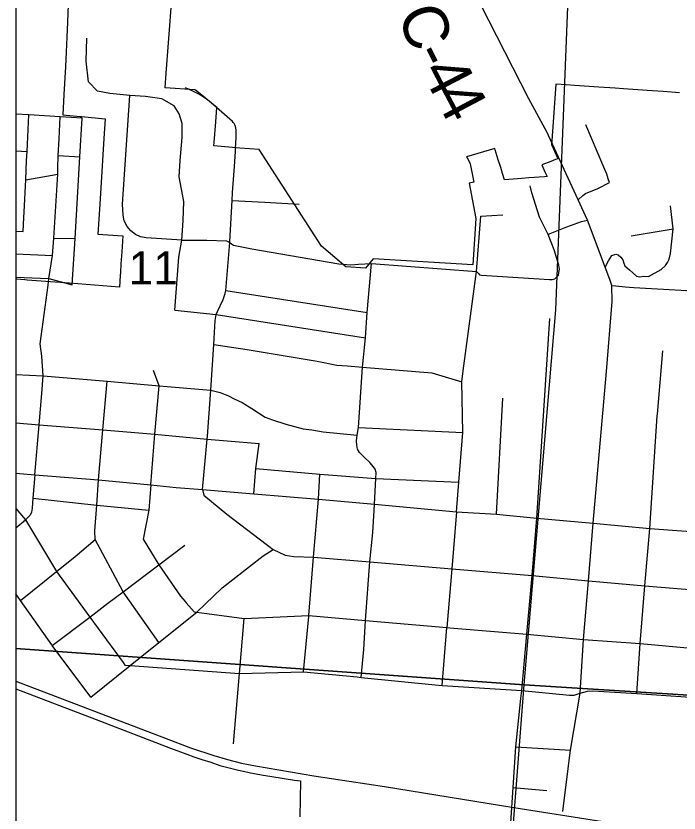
# Model space of a CAD drawing. Extents: x 39.8 to 73.8, y 13 to 35.
# Drawn here: x 41.863 to 42.701, y 32.071 to 33.079 of the extents above; entities that cross this region are included whole.
import ezdxf

# ---------------------------------------------------------------- set-up
doc = ezdxf.new("R2010")
doc.units = 0
for name, color, linetype in [('GM_X_City_Street', 7, 'Continuous'), ('GM_X_Corporation', 7, 'Continuous'), ('GM_X_County_Road', 7, 'Continuous'), ('GM_X_County_Road_Text', 7, 'Continuous'), ('GM_X_Rail_Line', 7, 'Continuous'), ('GM_X_Section_Text', 7, 'Continuous'), ('GM_X_State_Route', 7, 'Continuous'), ('GM_X_Township_Road', 7, 'Continuous')]:
    doc.layers.add(name, color=color, linetype=linetype)

msp = doc.modelspace()

# ---------------------------------------------------------------- linework, layer by layer
at = {"layer": 'GM_X_City_Street'}
for p, q in [((42.445, 32.756), (42.4502, 32.8257)), ((42.4502, 32.8257), (42.4779, 32.8274)), ((42.6401, 32.8009), (42.6933, 32.8099)), ((42.1281, 32.7318), (42.3066, 32.7041)), ((42.5212, 32.444), (42.5375, 32.6967)), ((42.6733, 32.5756), (42.6804, 32.6557)), ((42.4702, 32.4494), (42.4783, 32.5959)), ((42.2958, 32.5589), (42.4276, 32.5524)), ((41.863, 32.4566), (41.8751, 32.4421)), ((41.863, 32.4319), (41.8751, 32.4421)), ((42.2262, 32.2501), (42.2328, 32.32)), ((42.4014, 32.2327), (42.4072, 32.3062)), ((42.4945, 32.1553), (42.5635, 32.1509)), ((42.5539, 32.0735), (42.5623, 32.1412)), ((42.4911, 32.1038), (42.5336, 32.1001))]:
    msp.add_line(p, q, dxfattribs=at)
for points in [[(42.0636, 32.7071), (42.0687, 32.774), (42.0727, 32.7954), (42.0743, 32.8202), (42.0751, 32.8445), (42.0693, 32.8754), (42.0706, 32.8963), (42.0731, 32.9253), (42.0731, 32.9428), (42.0693, 32.9551), (42.0629, 32.9654), (42.0471, 32.9743), (42.0267, 32.9773), (42.007, 32.9782), (41.9815, 32.9807), (41.9662, 32.9837), (41.9545, 32.9955), (41.9516, 33.0217), (41.9524, 33.0509)], [(42.0727, 32.7954), (42.0274, 32.7984), (42.0204, 32.7999), (42.0142, 32.8027), (42.0083, 32.8072), (42.0037, 32.8129), (41.9999, 32.82), (41.9985, 32.8273), (41.9978, 32.8411), (42.007, 32.9782)], [(42.5734, 32.8466), (42.579, 32.8518), (42.5825, 32.8546), (42.598, 32.861), (42.6129, 32.8684), (42.6111, 32.8729), (42.6096, 32.879), (42.6043, 32.8906), (42.5828, 32.9414)], [(42.5353, 32.8027), (42.5243, 32.8248), (42.5147, 32.8555), (42.5125, 32.8643)], [(42.136, 32.8456), (42.1774, 32.8434), (42.221, 32.8409)], [(42.6073, 32.7616), (42.6114, 32.7693), (42.6159, 32.776), (42.6209, 32.7778), (42.6239, 32.7771), (42.6273, 32.7741), (42.6297, 32.7707), (42.6308, 32.7665), (42.6323, 32.7631), (42.6381, 32.7581), (42.6429, 32.754), (42.6468, 32.7499), (42.6511, 32.7491), (42.6558, 32.7499), (42.6623, 32.7497), (42.6782, 32.7583), (42.6837, 32.7635), (42.6862, 32.7674), (42.6882, 32.7717), (42.6899, 32.7786), (42.6933, 32.8099), (42.6898, 32.839)], [(42.0727, 32.7954), (42.1043, 32.7957), (42.1291, 32.7946), (42.1313, 32.7938), (42.1334, 32.7928), (42.1355, 32.7908), (42.1378, 32.7891), (42.1612, 32.7847), (42.2707, 32.7657), (42.286, 32.7644), (42.2957, 32.7654), (42.3122, 32.7662), (42.445, 32.756)], [(42.3154, 32.4537), (42.3158, 32.4617), (42.3178, 32.4944), (42.318, 32.5018), (42.3169, 32.5061), (42.3149, 32.5089), (42.3099, 32.5146), (42.3032, 32.5208), (42.297, 32.5271), (42.2943, 32.5313), (42.2936, 32.5363), (42.2934, 32.5418), (42.2941, 32.5492), (42.2958, 32.5589), (42.301, 32.6351), (42.3048, 32.6723), (42.3066, 32.7041), (42.3122, 32.7662)], [(42.616, 32.7381), (42.6207, 32.7378), (42.6326, 32.7364), (42.6437, 32.7356), (42.7479, 32.7297), (42.7652, 32.7282), (42.7801, 32.7247), (42.9726, 32.7075), (43.0218, 32.7079)], [(42.0636, 32.7071), (42.116, 32.7018), (42.3048, 32.6723)], [(42.0334, 32.4865), (42.0383, 32.5502), (42.0438, 32.6114), (42.0366, 32.6308)], [(41.9632, 32.4173), (41.9627, 32.4282), (41.9653, 32.4608), (41.9674, 32.4925), (41.9728, 32.5557), (41.9782, 32.6173)], [(42.4196, 32.4523), (42.4227, 32.4897), (42.4276, 32.5524), (42.4261, 32.6166)], [(42.109, 32.6059), (42.1208, 32.6031), (42.1315, 32.5988), (42.1386, 32.5951), (42.1487, 32.5902), (42.1609, 32.5826), (42.1779, 32.5718), (42.1869, 32.5683), (42.2041, 32.5631), (42.2258, 32.5573), (42.2366, 32.5557), (42.2511, 32.5535), (42.2941, 32.5492)], [(42.6473, 32.2227), (42.6514, 32.2858), (42.6575, 32.3586), (42.664, 32.4313), (42.6731, 32.5736), (42.6733, 32.5756)], [(41.863, 32.5647), (41.8923, 32.5621), (41.9728, 32.5557), (42.0383, 32.5502), (42.1047, 32.5442), (42.1702, 32.5387)], [(42.1634, 32.4749), (42.1661, 32.507), (42.1702, 32.5387)], [(42.1661, 32.507), (42.2468, 32.5), (42.3178, 32.4944), (42.4227, 32.4897)], [(42.2328, 32.32), (42.2328, 32.321), (42.2388, 32.3948), (42.2453, 32.4684), (42.2468, 32.5)], [(42.0334, 32.4865), (42.0307, 32.4541), (42.0237, 32.4175), (42.0434, 32.3852), (42.0709, 32.3457), (42.0769, 32.3388)], [(41.8843, 32.4696), (41.9653, 32.4608), (42.0307, 32.4541)], [(42.299, 32.243), (42.3023, 32.2783), (42.3045, 32.315), (42.3102, 32.389), (42.3139, 32.4259), (42.3154, 32.4537)], [(41.8688, 32.3402), (41.9141, 32.3767), (41.9376, 32.3956), (41.9632, 32.4173)], [(41.9089, 32.2833), (41.9562, 32.3192), (41.9792, 32.3366), (41.9983, 32.351), (42.0434, 32.3852), (42.0765, 32.4102)], [(42.0436, 32.2871), (41.9983, 32.351), (41.9632, 32.4173)], [(41.9576, 32.2181), (42.0074, 32.258), (42.0436, 32.2871), (42.0914, 32.3255), (42.1234, 32.356), (42.1753, 32.3967), (42.188, 32.4046)], [(41.9576, 32.2181), (41.9089, 32.2833), (41.9085, 32.2839), (41.8688, 32.3402), (41.863, 32.3485)], [(42.0769, 32.3388), (42.0782, 32.3373), (42.0882, 32.3259), (42.0914, 32.3255), (42.1514, 32.3174), (42.2328, 32.321), (42.3045, 32.315), (42.4072, 32.3062)], [(42.1379, 32.1588), (42.1453, 32.2479), (42.1514, 32.3174)], [(42.5801, 32.291), (42.6514, 32.2858), (42.7207, 32.2794), (42.8082, 32.2626), (42.9031, 32.2555), (42.909, 32.255)], [(42.5623, 32.1412), (42.5635, 32.1509), (42.5756, 32.2229)]]:
    msp.add_lwpolyline(points, dxfattribs=at)
at = {"layer": 'GM_X_Corporation'}
for points in [[(43.3481, 29.9766), (43.3525, 30.036), (43.3561, 30.0855), (43.3611, 30.1536), (43.3611, 30.1764), (43.4119, 30.9413), (43.4278, 31.1804), (43.4594, 31.6102), (43.4604, 31.6234), (43.4879, 31.9992), (43.5004, 32.1696), (43.5417, 32.788), (43.542, 32.7932), (43.5449, 32.8368), (43.546, 32.8532), (43.5465, 32.861), (43.5681, 33.1854), (43.5817, 33.4098), (43.6158, 33.865), (41.863, 33.865), (41.863, 28.2309)], [(41.9362, 33.2801), (41.9283, 33.0712), (41.9273, 33.0523), (41.9263, 33.0334), (41.9254, 33.0145), (41.9236, 32.9798), (41.9223, 32.9541), (41.944, 32.952), (41.9444, 32.952), (41.9456, 32.9518), (41.9758, 32.949), (41.9742, 32.9241), (41.9729, 32.9033), (41.9716, 32.8825), (41.9703, 32.8617), (41.9689, 32.8409), (41.9677, 32.822), (41.9665, 32.8031), (41.9979, 32.8011), (41.9966, 32.7806), (41.9957, 32.7655), (41.9949, 32.7547), (41.9946, 32.7507), (41.9936, 32.736), (41.9624, 32.7385), (41.9306, 32.741), (41.9007, 32.7434), (41.8771, 32.7452), (41.874, 32.7455), (41.8642, 32.7462), (41.863, 32.7464), (41.863, 32.2285), (41.9642, 32.1897), (42.0581, 32.1537), (42.0788, 32.1459), (42.0879, 32.1427), (42.0978, 32.1393), (42.109, 32.1358), (42.1204, 32.1318), (42.1342, 32.1282), (42.1442, 32.1257), (42.156, 32.1231), (42.1593, 32.1225), (42.1712, 32.1203), (42.1754, 32.1195), (42.1836, 32.1182), (42.2018, 32.1152), (42.2149, 32.1132), (42.2224, 32.1121), (42.2216, 32.0668)], [(42.7012, 32.9819), (42.6807, 32.9834), (42.6604, 32.9848), (42.6306, 32.9868), (42.6199, 32.9875), (42.5994, 32.989), (42.5687, 32.9911), (42.5582, 32.9918), (42.545, 32.9927), (42.5405, 32.9269), (42.5397, 32.9166), (42.5454, 32.9032), (42.5474, 32.8984), (42.5448, 32.8974), (42.5386, 32.895), (42.5274, 32.8908), (42.5312, 32.8821), (42.534, 32.8759), (42.5308, 32.8757), (42.5109, 32.8742), (42.502, 32.8736), (42.48, 32.872), (42.4777, 32.8796), (42.4754, 32.8872), (42.4724, 32.8972), (42.4686, 32.9097), (42.4681, 32.9115), (42.4324, 32.9008), (42.4329, 32.9001), (42.4369, 32.8922), (42.4415, 32.8689), (42.4399, 32.8686), (42.4354, 32.8677), (42.4441, 32.8231), (42.44, 32.7642), (42.3144, 32.7721), (42.3047, 32.76), (42.2797, 32.762), (42.2658, 32.7737), (42.249, 32.788), (42.1704, 32.9101), (42.1459, 32.912), (42.113, 32.9147), (42.1133, 32.919), (42.1154, 32.9449), (42.1169, 32.9631), (42.1028, 32.9747), (42.102, 32.9754), (42.0899, 32.9853), (42.0889, 32.9854), (42.0514, 32.9881), (42.0528, 33.0067), (42.0545, 33.0285), (42.0613, 33.1171)]]:
    msp.add_lwpolyline(points, dxfattribs=at)
for points in [[(41.863, 33.2861), (41.863, 32.2795), (42.505, 32.2334), (42.5452, 32.7074), (42.566, 33.2401)], [(43.567, 33.1836), (43.5036, 32.2603), (43.4969, 32.1712), (42.505, 32.2334), (42.5452, 32.7074), (42.566, 33.2401)], [(41.863, 32.2795), (41.863, 31.2545), (42.4262, 31.2112), (42.505, 32.2334)], [(42.505, 32.2334), (43.4969, 32.1712), (43.4282, 31.1846), (42.4262, 31.2112)]]:
    msp.add_lwpolyline(points, close=True, dxfattribs=at)
at = {"layer": 'GM_X_County_Road'}
for p, q in [((42.105, 32.548), (42.109, 32.6059)), ((41.863, 32.5012), (41.887, 32.4989)), ((42.4135, 32.3801), (42.5152, 32.3719)), ((42.5756, 32.2229), (42.5801, 32.291))]:
    msp.add_line(p, q, dxfattribs=at)
for points in [[(42.5359, 32.9279), (42.5342, 32.9315), (42.5108, 32.9743), (42.4605, 33.0731), (42.4552, 33.0827), (42.4505, 33.0936), (42.4476, 33.1026), (42.4441, 33.1205), (42.4386, 33.1514), (42.4341, 33.1736), (42.4275, 33.2003), (42.4257, 33.206), (42.415, 33.2417), (42.4147, 33.2426)], [(42.6131, 32.7459), (42.6073, 32.7616), (42.585, 32.8207), (42.5734, 32.8466), (42.5359, 32.9279)], [(42.1334, 32.7938), (42.136, 32.8456), (42.1365, 32.8558), (42.139, 32.8888), (42.1402, 32.9076), (42.1403, 32.9115)], [(42.5381, 32.8038), (42.559, 32.8122), (42.5776, 32.8191), (42.585, 32.8207)], [(42.546, 32.7487), (42.5483, 32.7513), (42.549, 32.7548), (42.5495, 32.759), (42.5489, 32.7639), (42.5428, 32.7833), (42.5353, 32.8027), (42.5381, 32.8038)], [(42.109, 32.6059), (42.1128, 32.6637), (42.1147, 32.6941), (42.116, 32.7018), (42.1175, 32.7055), (42.1248, 32.7205), (42.1275, 32.7283), (42.1281, 32.7318), (42.1334, 32.7928), (42.1334, 32.7938)], [(42.428, 32.6304), (42.445, 32.756), (42.4472, 32.7535)], [(42.4472, 32.7535), (42.4487, 32.7519), (42.4511, 32.7513), (42.537, 32.7458), (42.5405, 32.7459), (42.5436, 32.7466), (42.546, 32.7487)], [(42.5922, 32.4379), (42.609, 32.6294), (42.6162, 32.718), (42.616, 32.7381), (42.6131, 32.7459)], [(42.1128, 32.6637), (42.1553, 32.6573), (42.2437, 32.6427), (42.2683, 32.6376), (42.2818, 32.6367), (42.301, 32.6351)], [(42.301, 32.6351), (42.3885, 32.6278), (42.4261, 32.6166), (42.428, 32.6304)], [(41.863, 32.6256), (41.8973, 32.6242), (41.9782, 32.6173), (42.0438, 32.6114), (42.109, 32.6059)], [(42.0986, 32.4803), (42.1047, 32.5442), (42.105, 32.548)], [(41.887, 32.4989), (41.8843, 32.4696), (41.8836, 32.4567), (41.8825, 32.4517), (41.881, 32.448), (41.8751, 32.4421), (41.9141, 32.3767), (41.9562, 32.3192), (41.9983, 32.2617)], [(41.887, 32.4989), (41.9674, 32.4925), (42.0334, 32.4865), (42.0655, 32.4831), (42.0986, 32.4803)], [(42.0986, 32.4803), (42.1002, 32.4733), (42.1294, 32.4492), (42.188, 32.4046), (42.2032, 32.3975), (42.2142, 32.3958), (42.2388, 32.3948), (42.3102, 32.389), (42.4135, 32.3801)], [(42.0986, 32.4803), (42.1634, 32.4749), (42.2453, 32.4684), (42.3158, 32.4617), (42.4196, 32.4523), (42.4702, 32.4494), (42.5212, 32.444)], [(42.4196, 32.4523), (42.4135, 32.3801), (42.4072, 32.3062), (42.4111, 32.3058)], [(42.5801, 32.291), (42.5863, 32.365), (42.5922, 32.4379)], [(42.5152, 32.3719), (42.5863, 32.365), (42.6575, 32.3586), (42.7239, 32.3531)], [(42.4111, 32.3058), (42.5086, 32.2975), (42.5801, 32.291)], [(41.9983, 32.2617), (42.0006, 32.2585), (42.0074, 32.258), (42.1453, 32.2479), (42.2262, 32.2501), (42.294, 32.2435)], [(42.294, 32.2435), (42.299, 32.243), (42.3925, 32.2336)], [(42.3925, 32.2336), (42.4014, 32.2327), (42.5021, 32.2264)], [(42.5021, 32.2264), (42.5625, 32.2203), (42.5684, 32.2207), (42.5756, 32.2229)], [(42.5756, 32.2229), (42.5849, 32.2254), (42.5918, 32.226), (42.6473, 32.2227), (42.7153, 32.218)]]:
    msp.add_lwpolyline(points, dxfattribs=at)
at = {"layer": 'GM_X_Rail_Line'}
msp.add_lwpolyline([(41.863, 32.2382), (42.0529, 32.1656), (42.0836, 32.154), (42.1128, 32.1442), (42.1302, 32.1391), (42.1479, 32.1346), (42.1658, 32.1312), (42.2395, 32.1187), (42.3284, 32.1049), (42.4921, 32.0784), (42.6044, 32.0607)], dxfattribs=at)
at = {"layer": 'GM_X_State_Route'}
for points in [[(42.501, 32.2163), (42.5021, 32.2264), (42.5086, 32.2975), (42.5152, 32.3719), (42.5212, 32.444), (42.5922, 32.4379), (42.664, 32.4313), (42.7326, 32.4261), (42.7439, 32.4253), (42.7509, 32.4279), (42.7568, 32.4329)], [(42.4854, 32.0251), (42.486, 32.0321), (42.4867, 32.0392), (42.4881, 32.059), (42.4911, 32.1038), (42.4945, 32.1553), (42.501, 32.2163)]]:
    msp.add_lwpolyline(points, dxfattribs=at)
at = {"layer": 'GM_X_Township_Road'}
for p, q in [((41.9175, 32.9238), (41.919, 32.9515)), ((41.863, 32.9086), (41.877, 32.9078)), ((41.9163, 32.9025), (41.9439, 32.9008)), ((41.8753, 32.8717), (41.9158, 32.879)), ((41.863, 32.8071), (41.8722, 32.8065)), ((41.9109, 32.798), (41.9376, 32.7976)), ((41.863, 32.7781), (41.9091, 32.7763)), ((41.863, 32.7487), (41.9046, 32.7471))]:
    msp.add_line(p, q, dxfattribs=at)
for points in [[(42.1403, 32.9115), (42.141, 32.9253), (42.1413, 32.9315), (42.1412, 32.9345), (42.1408, 32.9375), (42.1398, 32.9405), (42.1386, 32.9428), (42.1376, 32.9443), (42.1365, 32.9455), (42.1096, 32.9692), (42.1073, 32.9711), (42.1039, 32.9737), (42.0994, 32.9767), (42.0942, 32.9799), (42.0865, 32.9838), (42.077, 32.9881)], [(41.9046, 32.7471), (41.9341, 32.7392), (41.9376, 32.7976), (41.9439, 32.9008), (41.9468, 32.9498), (41.919, 32.9515), (41.8791, 32.9538), (41.863, 32.9548)], [(41.8764, 32.8963), (41.877, 32.9078), (41.8791, 32.9538)], [(41.9159, 32.8866), (41.9163, 32.9025), (41.9175, 32.9238)], [(41.8734, 32.8313), (41.8753, 32.8717), (41.8764, 32.8963)], [(41.9035, 32.7386), (41.9046, 32.7471), (41.9091, 32.7763), (41.9109, 32.798), (41.9158, 32.879), (41.9159, 32.8866)], [(41.8722, 32.8065), (41.873, 32.824), (41.8734, 32.8313)], [(41.8955, 32.6018), (41.8973, 32.6242), (41.8958, 32.649), (41.8936, 32.6645), (41.9035, 32.7386)], [(41.887, 32.4989), (41.8923, 32.5621), (41.8955, 32.6018)]]:
    msp.add_lwpolyline(points, dxfattribs=at)

# ---------------------------------------------------------------- texts
at = {"layer": 'GM_X_County_Road_Text'}
for s, rotation, p in [('C', 289.1101, (42.3449, 33.0825)), ('-', 296.6859, (42.3634, 33.0309)), ('4', 297.4483, (42.3743, 33.0093)), ('4', 297.8541, (42.3906, 32.9778))]:
    msp.add_text(s, height=0.0568, rotation=rotation, dxfattribs=at).set_placement(p)
at = {"layer": 'GM_X_Section_Text'}
msp.add_text('11', height=0.04186, rotation=0, dxfattribs=at).set_placement((42.0053, 32.7396))

doc.saveas('drawing.dxf')
